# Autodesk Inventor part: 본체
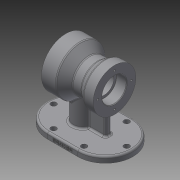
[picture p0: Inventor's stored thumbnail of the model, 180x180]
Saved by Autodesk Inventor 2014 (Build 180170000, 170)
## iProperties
Created: 2020-01
Part Number: 본체
Material: Generic
Document SubType Name: Modeling
Designer: kh
Density: 1 g/cm^3
Appearance: Default
Author: kh
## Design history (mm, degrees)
sketch "스케치1"
  geometry: L1 (-25, 0)-(25, 0); L2 (-25, -45)-(25, -45); L3 (25, 45)-(-25, 45); A1 r 45 centre (-25, 0) between (-25, 45) and (-25, -45); A2 r 45 centre (25, 0) between (25, -45) and (25, 45); 2 further points
  constraints: 8 end point, 4 point on circle, 4 tangent, 2 centre point, 1 coincident, 1 horizontal, 1 midpoint, 1 parallel
  dimensions: "d0" = 50 distance of L1.end L1.start; "d1" = 45 radius of A1
extrude "돌출1" new body sketch "스케치1" distance "d2" = 10; taper "d3" = 0 deg
sketch "스케치2"
  geometry: L1 (25, 45)-(-25, 45) reference; 3 further points
  dimensions: "d4" = 10 distance from line of L1 point (-25, 35); "d5" = 10 distance of L1.start point (25, 35); "d6" = 50 distance of point (25, 35) point (-25, 35)
hole "구멍1" sketch "스케치2" at (25, 35) diameter "d7" = 9; stored, may be unused: countersink angle "d11" = 90 deg, drill point angle "d13" = 118 deg; dims "d8" = 6, "d9" = 4, "d10" = 2, "d12" = 8
node "작업 평면1"
sketch "스케치4"
  geometry: L1 (-40, 0)-(40, 0); L2 (-40, 0)-(-40, 40); L3 (-40, 40)-(-16, 40); L4 (-16, 40)-(-1.103, 27.5); L5 (-1.103, 27.5)-(13.289, 27.5); L6 (13.289, 27.5)-(24, 35); L7 (24, 35)-(40, 35); L8 (40, 35)-(40, 0); 2 further points
  constraints: 16 end point, 3 parallel, 2 coincident, 2 perpendicular, 1 horizontal, 1 midpoint
  dimensions: "d21" = 80 distance of L1.start L1.end; "d22" = 80 diameter of L3 L1; "d23" = 70 diameter of L7 L1; "d24" = 35 deg angle of L5 L6; "d25" = 40 deg angle of L5 L4; "d26" = 24 distance of L2.end L3.end; "d27" = 16 distance of L6.end L7.end; "d60" = 55 diameter of L5 L1
revolve "회전1" sketch "스케치4" stored, may be unused: angle "d28" = 90 deg
node "작업 평면3"
sketch "스케치7"
  geometry: L1 (9.933, -5)-(80, -5); L2 (80, -5)-(80, 5); L3 (80, 5)-(9.933, 5); L4 (9.933, 5)-(9.933, -5); L5 (80, 45)-(80, -45) reference; 3 further points
  constraints: 8 end point, 2 midpoint, 2 parallel, 1 coincident, 1 collinear, 1 horizontal, 1 perpendicular
  dimensions: "d33" = 10 distance of L1.end L2.end
sketch "스케치8"
  geometry: L1 (25, 45)-(-25, 45) reference; L2 (-70, 41.595)-(-70, -56.97); C1 r 16 at (-12, 0); A1 r 45 centre (-25, 0) between (-25, 45) and (-25, -45) reference; 1 further point
  constraints: 2 end point, 1 centre point, 1 horizontal alignment, 1 perpendicular, 1 tangent
  dimensions: "d34" = 16 radius of C1; "d35" = 58 distance from line of C1.centre L2
extrude "돌출2" join sketch "스케치8" distance "d36" = 76.25; taper "d37" = 0 deg; dims "d28" = 90 deg
extrude "돌출3" join sketch "스케치7" distance "d38" = 48; taper "d39" = 0 deg
hole "구멍2" diameter "d42" = 32; stored, may be unused: countersink angle "d46" = 90 deg, drill point angle "d48" = 118 deg; dims "d43" = 6, "d44" = 40, "d45" = 17, "d47" = 8, "d51" = 10, "d52" = 10
hole "구멍3" diameter "d53" = 9; stored, may be unused: countersink angle "d57" = 90 deg, drill point angle "d59" = 118 deg; dims "d49" = 10, "d50" = 10, "d54" = 6, "d55" = 52, "d56" = 20, "d58" = 8
sketch "스케치9"
  geometry: C1 r 26 at (0, 0) reference; 2 further points
  constraints: 1 horizontal alignment
  dimensions: "d61" = 33 distance of point (33, 0) C1.centre
hole "구멍4" sketch "스케치9" at (33, 0) diameter "d62" = 3.242; stored, may be unused: countersink angle "d66" = 90 deg, drill point angle "d68" = 118 deg; dims "d63" = 9, "d64" = 52, "d65" = 20, "d67" = 11
sketch "스케치10"
  geometry: C1 r 20 at (0, 0) reference; 2 further points
  constraints: 1 vertical alignment
  dimensions: "d72" = 27.5 distance of point (0, 27.5) C1.centre
hole "구멍5" sketch "스케치10" at (0, 27.5) diameter "d73" = 3.242; stored, may be unused: countersink angle "d77" = 90 deg, drill point angle "d79" = 118 deg; dims "d74" = 9, "d75" = 52, "d76" = 20, "d78" = 11
sketch "스케치12"
  geometry: L1 (0, 0)-(-45, 0) reference; L2 (-45, 0)-(-45, 10) reference; 2 further points
  constraints: 1 other
  dimensions: "d83" = 4 distance from line of L1 point (25, 4); "d84" = 70 distance from line of L2 point (25, 4)
feature "엠보싱1" sketch "스케치12" dims "d0" = 50, "d1" = 45, "d85" = 0.5, "d86" = 0
fillet "모깎기1" dims "d87" = 3
fillet "모깎기2" dims "d88" = 3
fillet "모깎기3" dims "d89" = 3
fillet "모깎기4" dims "d90" = 3
chamfer "모따기1" distance "d91" = 1; stored, may be unused: second distance "d92" = 2, angle "d93" = 45 deg
fillet "모깎기5" dims "d94" = 0.3
node "솔리드1"
pattern_circular "원형 패턴1" dims angle "d15" = 180 deg
mirror "대칭1"
pattern_circular "원형 패턴2" dims angle "d70" = 360 deg
pattern_circular "원형 패턴3" dims angle "d81" = 360 deg
